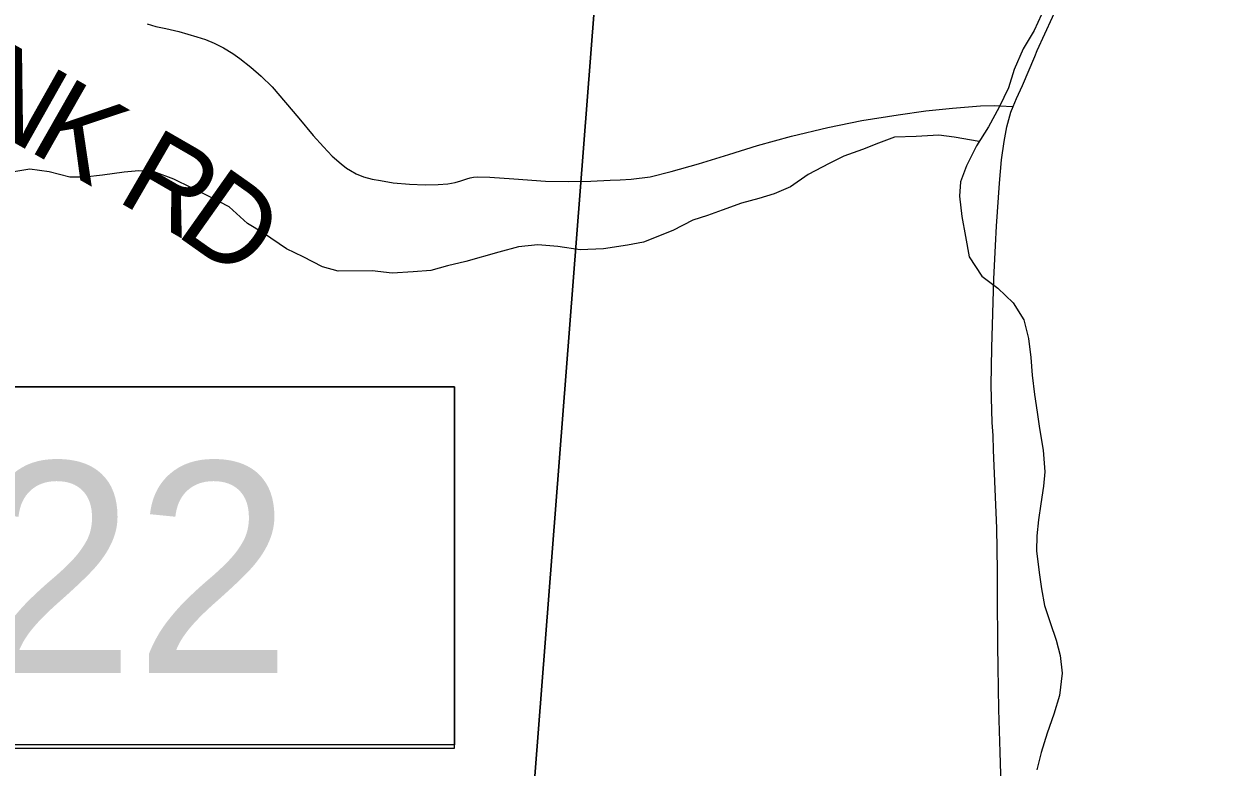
# Model space of a CAD drawing. Extents: x 0 to 34, y 0 to 22.
# Drawn here: x 7.074 to 7.868, y 17.019 to 17.513 of the extents above; entities that cross this region are included whole.
import ezdxf

# ---------------------------------------------------------------- set-up
doc = ezdxf.new("R2010")
doc.units = 0
for name, color, linetype in [('GM_X_Corporation', 7, 'Continuous'), ('GM_X_County_Road', 7, 'Continuous'), ('GM_X_County_Road_Text', 7, 'Continuous'), ('GM_X_Minor_River', 7, 'Continuous'), ('SH_Text', 7, 'Continuous')]:
    doc.layers.add(name, color=color, linetype=linetype)

msp = doc.modelspace()

# ---------------------------------------------------------------- linework, layer by layer
at = {"layer": 'GM_X_Corporation'}
for points in [[(6.43864, 17.7441), (7.4643, 17.67029), (7.3858, 16.65576), (6.39117, 16.72034)], [(8.46287, 17.60104), (8.3827, 16.59195), (7.3858, 16.65576), (7.4643, 17.67029)]]:
    msp.add_lwpolyline(points, close=True, dxfattribs=at)
at = {"layer": 'GM_X_County_Road'}
for points in [[(7.73096, 17.45783), (7.73321, 17.46304), (7.73728, 17.47161), (7.74546, 17.49094), (7.74703, 17.49491), (7.75712, 17.517), (7.76541, 17.53394), (7.77415, 17.55083), (7.77717, 17.55773), (7.79606, 17.6009), (7.80155, 17.61302)], [(7.15629, 17.51272), (7.162, 17.51098), (7.16861, 17.50944), (7.17728, 17.5075), (7.18915, 17.50408), (7.19497, 17.50214), (7.20068, 17.49979), (7.20692, 17.49665), (7.21317, 17.49288), (7.21781, 17.4896), (7.22505, 17.48382), (7.23187, 17.47781), (7.23909, 17.47079), (7.25689, 17.4499), (7.2664, 17.43856), (7.27317, 17.43093), (7.27911, 17.42483), (7.28488, 17.41962), (7.28855, 17.41678), (7.29118, 17.41527), (7.29495, 17.41305), (7.2999, 17.4111), (7.30563, 17.40954), (7.3111, 17.40849), (7.31943, 17.40706), (7.33024, 17.40615), (7.34073, 17.40573), (7.34938, 17.40589), (7.35569, 17.40641), (7.36066, 17.40731), (7.3645, 17.40833), (7.36845, 17.40968), (7.3707, 17.41024), (7.37285, 17.41073), (7.37517, 17.41097), (7.38376, 17.4108), (7.39962, 17.40966), (7.42053, 17.40816), (7.436, 17.40796), (7.45065, 17.40816), (7.46352, 17.40874), (7.47024, 17.40902), (7.47752, 17.40953), (7.49003, 17.4111), (7.50395, 17.41451), (7.52213, 17.41962), (7.54231, 17.42587), (7.56134, 17.43184), (7.58378, 17.43809), (7.60794, 17.44378), (7.63067, 17.44832), (7.65473, 17.45217), (7.67311, 17.45484), (7.69085, 17.45671), (7.70939, 17.45813), (7.71877, 17.45835), (7.7219, 17.45822), (7.73096, 17.45783)], [(7.72339, 16.99249), (7.72232, 17.02872), (7.72147, 17.05714), (7.72115, 17.08556), (7.72085, 17.09942), (7.72063, 17.13305), (7.72063, 17.14946), (7.72012, 17.1776), (7.71804, 17.22938), (7.71764, 17.23922), (7.71707, 17.24774), (7.71651, 17.2725), (7.71681, 17.29747), (7.71807, 17.34293), (7.71939, 17.36545), (7.72003, 17.37822), (7.72186, 17.40678), (7.72331, 17.42226), (7.72503, 17.43457), (7.72677, 17.44427), (7.72935, 17.45407), (7.73096, 17.45783)]]:
    msp.add_lwpolyline(points, dxfattribs=at)
at = {"layer": 'GM_X_Minor_River'}
for p, q in [((7.6522, 17.43727), (7.64164, 17.43339)), ((7.66657, 17.43778), (7.6522, 17.43727)), ((7.6817, 17.43868), (7.66657, 17.43778)), ((7.69193, 17.43725), (7.6817, 17.43868)), ((7.7085, 17.43455), (7.69193, 17.43725)), ((7.63108, 17.42912), (7.61863, 17.42484)), ((7.64164, 17.43339), (7.63108, 17.42912)), ((7.61863, 17.42484), (7.60884, 17.41982)), ((7.07839, 17.41612), (7.0663, 17.41412)), ((7.09127, 17.41434), (7.07839, 17.41612)), ((7.10493, 17.41068), (7.09127, 17.41434)), ((7.14084, 17.41404), (7.12648, 17.41201)), ((7.15067, 17.41489), (7.14084, 17.41404)), ((7.16089, 17.41422), (7.15067, 17.41489)), ((7.1738, 17.40941), (7.16089, 17.41422)), ((7.60884, 17.41982), (7.5949, 17.4125)), ((7.11476, 17.41077), (7.10493, 17.41068)), ((7.12648, 17.41201), (7.11476, 17.41077)), ((7.19736, 17.39788), (7.1738, 17.40941)), ((7.5949, 17.4125), (7.58324, 17.40443)), ((7.21066, 17.39118), (7.19736, 17.39788)), ((7.57231, 17.39979), (7.56212, 17.39666)), ((7.58324, 17.40443), (7.57231, 17.39979)), ((7.22287, 17.37992), (7.21066, 17.39118)), ((7.5508, 17.39353), (7.53797, 17.38886)), ((7.56212, 17.39666), (7.5508, 17.39353)), ((7.51835, 17.38224), (7.50517, 17.3753)), ((7.52817, 17.38536), (7.51835, 17.38224)), ((7.53797, 17.38886), (7.52817, 17.38536)), ((7.23352, 17.37358), (7.22287, 17.37992)), ((7.24874, 17.36311), (7.23352, 17.37358)), ((7.50517, 17.3753), (7.48556, 17.36754)), ((7.41558, 17.36577), (7.40273, 17.36451)), ((7.42883, 17.36475), (7.41558, 17.36577)), ((7.47499, 17.36555), (7.45912, 17.36313)), ((7.48556, 17.36754), (7.47499, 17.36555)), ((7.25976, 17.3579), (7.24874, 17.36311)), ((7.27268, 17.3512), (7.25976, 17.3579)), ((7.38952, 17.36098), (7.36762, 17.35472)), ((7.40273, 17.36451), (7.38952, 17.36098)), ((7.44361, 17.36261), (7.42883, 17.36475)), ((7.45912, 17.36313), (7.44361, 17.36261)), ((7.28292, 17.34826), (7.27268, 17.3512)), ((7.35554, 17.35196), (7.34459, 17.34882)), ((7.36762, 17.35472), (7.35554, 17.35196)), ((7.30563, 17.34847), (7.28292, 17.34826)), ((7.31888, 17.34707), (7.30563, 17.34847)), ((7.33287, 17.34796), (7.31888, 17.34707)), ((7.34459, 17.34882), (7.33287, 17.34796))]:
    msp.add_line(p, q, dxfattribs=at)
msp.add_lwpolyline([(7.74987, 17.51888), (7.74504, 17.50822), (7.73758, 17.49603), (7.73164, 17.48233), (7.72797, 17.47017), (7.72165, 17.45723), (7.71457, 17.44428), (7.70673, 17.43171), (7.70004, 17.41838), (7.69597, 17.40773), (7.69529, 17.39825), (7.69693, 17.38463), (7.69931, 17.37139), (7.7017, 17.35777), (7.71013, 17.34496), (7.7208, 17.3371), (7.7311, 17.32734), (7.73801, 17.31604), (7.74114, 17.30356), (7.74277, 17.29107), (7.74363, 17.27933), (7.74525, 17.26646), (7.74687, 17.25473), (7.74848, 17.24375), (7.75087, 17.22938), (7.75213, 17.21499), (7.75108, 17.2055), (7.74929, 17.19374), (7.74787, 17.18312), (7.74682, 17.1725), (7.74653, 17.16264), (7.74817, 17.14826), (7.74978, 17.13728), (7.75177, 17.12631), (7.75565, 17.11498), (7.75953, 17.10327), (7.76227, 17.09306), (7.76351, 17.08133), (7.76174, 17.06653), (7.75807, 17.05399), (7.75364, 17.04145), (7.74959, 17.02853), (7.74666, 17.01713)], dxfattribs=at)
at = {"layer": 'SH_Text'}
for points in [[(7.36019, 17.27147), (5.9977, 17.27147), (5.9977, 17.03147), (7.36019, 17.03147)], [(5.9977, 17.27147), (7.36019, 17.27147), (7.36019, 17.03371), (5.9977, 17.03371)]]:
    msp.add_lwpolyline(points, close=True, dxfattribs=at)

# ---------------------------------------------------------------- texts
at = {"layer": 'GM_X_County_Road_Text'}
for s, rotation, p in [('N', 330.60891, (7.03263, 17.45357)), ('K', 330.37079, (7.07614, 17.42907)), ('R', 329.97675, (7.13472, 17.39574)), ('D', 324.7579, (7.17397, 17.37313))]:
    msp.add_text(s, height=0.05682, rotation=rotation, dxfattribs=at).set_placement(p)
at = {"layer": 'SH_Text'}
msp.add_text('HOC-328-6.22', height=0.14, dxfattribs=at).set_placement((6.03465, 17.08147))

doc.saveas('drawing.dxf')
